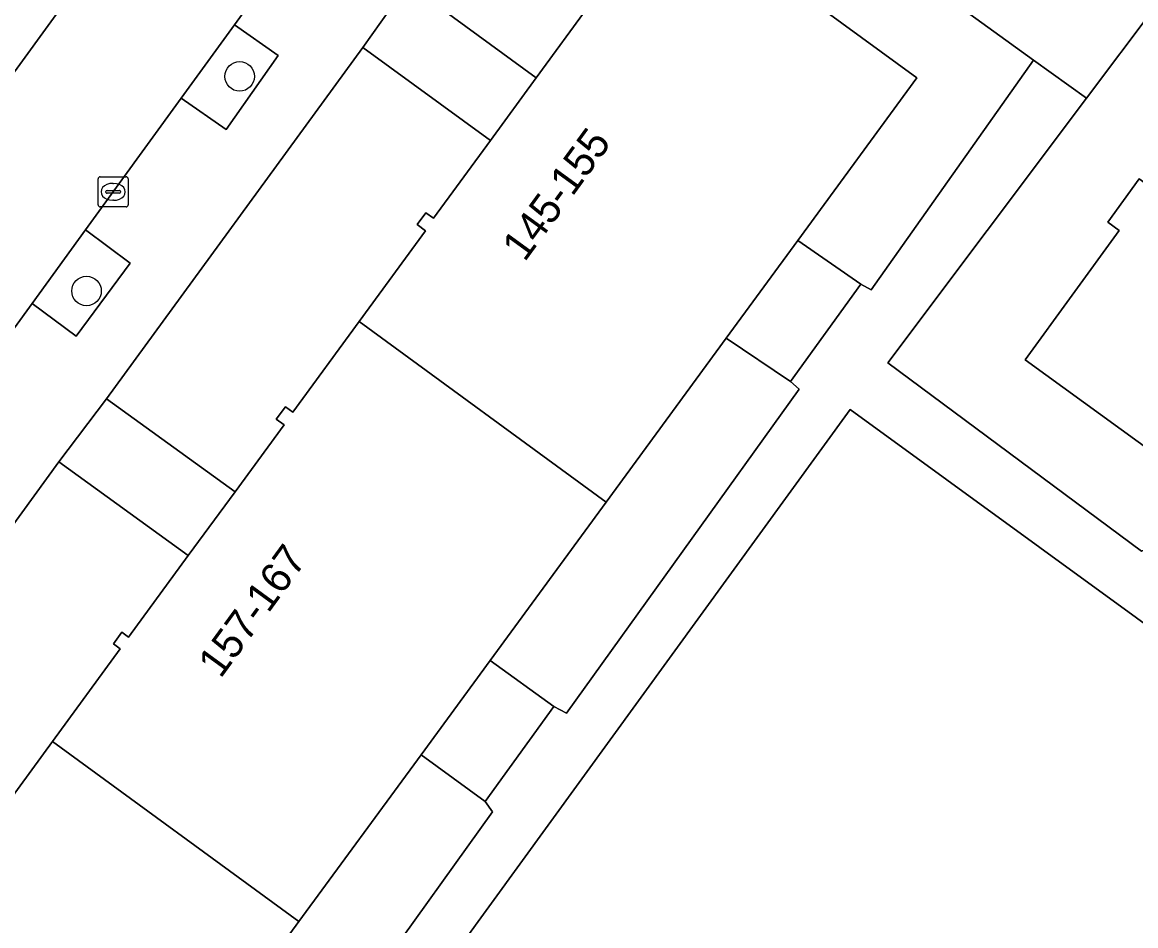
# Model space of a CAD drawing. Extents: x 160102 to 160934, y 382045 to 382923.
# Drawn here: x 160308.9 to 160345.72, y 382406.82 to 382436.72 of the extents above; entities that cross this region are included whole.
import ezdxf

# ---------------------------------------------------------------- set-up
doc = ezdxf.new("R2010")
doc.units = 0
for name, color, linetype in [('IMGEO_Boom', 7, 'Continuous'), ('IMGEO_Groenvoorziening', 7, 'Continuous'), ('IMGEO_Kolk', 7, 'Continuous'), ('IMGEO_Pand', 7, 'Continuous'), ('IMGEO_Pand_nummerreeks', 7, 'Continuous'), ('IMGEO_Parkeervlak_open', 7, 'Continuous'), ('IMGEO_Rijbaan_lokaal_open', 7, 'Continuous'), ('IMGEO_Voetpad_op_trap', 7, 'Continuous'), ('IMGEO_Voetpad_open', 7, 'Continuous')]:
    doc.layers.add(name, color=color, linetype=linetype)

msp = doc.modelspace()

# ---------------------------------------------------------------- linework, layer by layer
at = {"layer": 'IMGEO_Boom'}
for centre in [(160316.088, 382434.925), (160311.025, 382427.824)]:
    msp.add_circle(centre, 0.489, dxfattribs=at)
at = {"layer": 'IMGEO_Groenvoorziening'}
for points in [[(160326.042, 382443.886), (160321.653, 382437.992), (160325.889, 382434.874), (160327.67, 382437.308), (160327.431, 382437.483), (160327.719, 382437.877), (160327.954, 382437.705), (160329.995, 382440.493), (160329.751, 382440.671), (160330.034, 382441.058), (160332.743, 382439.075), (160333.021, 382439.455), (160334.448, 382438.411), (160334.173, 382438.035), (160338.483, 382434.88), (160334.541, 382429.494), (160336.63, 382428.051), (160336.971, 382427.863), (160342.342, 382435.462), (160330.141, 382444.298)], [(160370.829, 382398.747), (160336.272, 382423.908), (160301.535, 382376.068), (160301.385, 382375.861), (160326.781, 382357.302), (160333.47, 382352.414)]]:
    msp.add_lwpolyline(points, dxfattribs=at)
for points in [[(160345.836, 382431.539), (160346.277, 382431.219), (160348.196, 382433.864), (160348.496, 382433.646), (160348.355, 382433.452), (160351.228, 382431.367), (160351.397, 382431.599), (160351.776, 382431.324), (160351.609, 382431.094), (160354.123, 382429.27), (160355.13, 382430.78), (160346.323, 382437.183), (160344.086, 382434.199), (160337.524, 382425.446), (160345.91, 382419.22), (160346.099, 382419.291), (160347.73, 382421.428), (160342.062, 382425.541), (160345.171, 382429.825), (160344.791, 382430.1)], [(160314.157, 382434.207), (160315.637, 382433.164), (160317.362, 382435.613), (160315.915, 382436.632)], [(160322.237, 382429.818), (160321.957, 382430.023), (160322.243, 382430.415), (160322.493, 382430.232), (160324.377, 382432.807), (160320.164, 382435.884), (160311.684, 382424.258), (160315.935, 382421.18), (160317.556, 382423.395), (160317.3, 382423.582), (160317.602, 382423.994), (160317.845, 382423.816), (160320.041, 382426.817)], [(160309.224, 382427.412), (160310.684, 382426.332), (160312.472, 382428.749), (160310.991, 382429.844)], [(160334.588, 382424.579), (160334.297, 382424.828), (160332.174, 382426.259), (160328.208, 382420.84), (160324.37, 382415.595), (160326.472, 382414.075), (160326.893, 382413.858)], [(160312.135, 382415.982), (160311.912, 382416.146), (160312.196, 382416.535), (160312.417, 382416.373), (160314.389, 382419.068), (160310.105, 382422.17), (160301.387, 382410.162), (160305.61, 382407.024), (160307.41, 382409.484), (160307.146, 382409.677), (160307.414, 382410.043), (160307.657, 382409.865), (160309.896, 382412.923)], [(160324.45, 382410.594), (160324.208, 382410.933), (160322.085, 382412.472), (160318.049, 382406.957), (160314.189, 382401.682), (160316.293, 382400.219), (160316.804, 382399.911)]]:
    msp.add_lwpolyline(points, close=True, dxfattribs=at)
at = {"layer": 'IMGEO_Kolk'}
for p, q in [((160311.405, 382430.679), (160311.405, 382431.531)), ((160311.48, 382431.605), (160312.332, 382431.605)), ((160312.406, 382431.531), (160312.406, 382430.679)), ((160311.893, 382431.385), (160311.918, 382431.385)), ((160311.664, 382431.099), (160311.664, 382431.111)), ((160312.102, 382431.062), (160311.704, 382431.062)), ((160311.707, 382431.148), (160312.105, 382431.148)), ((160311.916, 382430.825), (160311.891, 382430.825)), ((160312.148, 382431.111), (160312.148, 382431.099)), ((160312.332, 382430.605), (160311.48, 382430.605))]:
    msp.add_line(p, q, dxfattribs=at)
for points in [[(160311.405, 382430.679), (160311.405, 382431.531)], [(160311.48, 382431.605), (160312.332, 382431.605)], [(160312.406, 382431.531), (160312.406, 382430.679)], [(160312.332, 382430.605), (160311.48, 382430.605)]]:
    msp.add_lwpolyline(points, dxfattribs=at)
for centre, radius, start, end in [((160311.482, 382431.529), 0.0765, 91.552, 178.448), ((160311.482, 382431.529), 0.0765, 91.552, 178.448), ((160312.33, 382431.529), 0.0765, 1.552, 88.448), ((160312.33, 382431.529), 0.0765, 1.552, 88.448), ((160311.704, 382431.108), 0.0403, 85.8775, 175.7526), ((160311.701, 382431.098), 0.0366, 178.938, 274.7102), ((160312.105, 382431.105), 0.043, 264.8664, 352.4533), ((160312.109, 382431.11), 0.0386, 1.7309, 96.639), ((160311.482, 382430.681), 0.0765, 181.552, 268.448), ((160311.482, 382430.681), 0.0765, 181.552, 268.448), ((160312.33, 382430.681), 0.0765, 271.552, 358.448), ((160312.33, 382430.681), 0.0765, 271.552, 358.448)]:
    msp.add_arc(centre, radius, start, end, dxfattribs=at)
for centre, major_axis, ratio, start_param, end_param in [((160311.892, 382431.105), (-0.387, 0.002), 0.722429, 4.712389, 7.853982), ((160311.917, 382431.105), (-0.39, 0.002), 0.717154, 1.570796, 4.712389)]:
    msp.add_ellipse(centre, major_axis=major_axis, ratio=ratio, start_param=start_param, end_param=end_param, dxfattribs=at)
at = {"layer": 'IMGEO_Pand'}
for points in [[(160338.483, 382434.88), (160334.173, 382438.035), (160334.448, 382438.411), (160333.021, 382439.455), (160332.743, 382439.075), (160330.034, 382441.058), (160329.751, 382440.671), (160329.995, 382440.493), (160327.954, 382437.705), (160327.719, 382437.877), (160327.431, 382437.483), (160327.67, 382437.308), (160325.889, 382434.874), (160324.377, 382432.807), (160322.493, 382430.232), (160322.243, 382430.415), (160321.957, 382430.023), (160322.237, 382429.818), (160320.041, 382426.817), (160328.208, 382420.84), (160332.174, 382426.259), (160334.541, 382429.494)], [(160356.176, 382427.78), (160354.123, 382429.27), (160351.609, 382431.094), (160351.776, 382431.324), (160351.397, 382431.599), (160351.228, 382431.367), (160348.355, 382433.452), (160348.496, 382433.646), (160348.196, 382433.864), (160346.277, 382431.219), (160345.836, 382431.539), (160344.791, 382430.1), (160345.171, 382429.825), (160342.062, 382425.541), (160347.73, 382421.428), (160350.837, 382419.173), (160356.188, 382415.289), (160362.154, 382423.509), (160359.103, 382425.723), (160359.222, 382425.887), (160358.82, 382426.179), (160358.668, 382425.971)], [(160328.208, 382420.84), (160320.041, 382426.817), (160317.845, 382423.816), (160317.602, 382423.994), (160317.3, 382423.582), (160317.556, 382423.395), (160315.935, 382421.18), (160314.389, 382419.068), (160312.417, 382416.373), (160312.196, 382416.535), (160311.912, 382416.146), (160312.135, 382415.982), (160309.896, 382412.923), (160318.049, 382406.957), (160322.085, 382412.472), (160324.37, 382415.595)], [(160318.049, 382406.957), (160309.896, 382412.923), (160307.657, 382409.865), (160307.414, 382410.043), (160307.146, 382409.677), (160307.41, 382409.484), (160305.61, 382407.024), (160304.093, 382404.95), (160302.264, 382402.451), (160302.04, 382402.614), (160301.746, 382402.213), (160301.968, 382402.051), (160299.756, 382399.029), (160307.89, 382393.076), (160311.897, 382398.552), (160314.189, 382401.682)]]:
    msp.add_lwpolyline(points, close=True, dxfattribs=at)
at = {"layer": 'IMGEO_Parkeervlak_open'}
msp.add_lwpolyline([(160294.103, 382415.076), (160350.285, 382492.403), (160348.458, 382493.72), (160295.236, 382420.526), (160294.487, 382419.495)], dxfattribs=at)
at = {"layer": 'IMGEO_Rijbaan_lokaal_open'}
msp.add_lwpolyline([(160353.587, 382490.022), (160350.285, 382492.403), (160294.103, 382415.076), (160282.644, 382399.239), (160286.754, 382396.408), (160289.282, 382399.909), (160291.056, 382402.365), (160297.372, 382411.107), (160299.14, 382413.539), (160304.095, 382420.356), (160305.885, 382422.819), (160309.224, 382427.412), (160310.991, 382429.844), (160314.157, 382434.207), (160315.915, 382436.632), (160319.987, 382442.247), (160321.768, 382444.703), (160324.87, 382448.973), (160324.923, 382449.066), (160334.935, 382462.721)], dxfattribs=at)
at = {"layer": 'IMGEO_Voetpad_op_trap'}
for points in [[(160336.63, 382428.051), (160334.541, 382429.494), (160332.174, 382426.259), (160334.297, 382424.828)], [(160326.472, 382414.075), (160324.37, 382415.595), (160322.085, 382412.472), (160324.208, 382410.933)]]:
    msp.add_lwpolyline(points, close=True, dxfattribs=at)
at = {"layer": 'IMGEO_Voetpad_open'}
for points in [[(160320.164, 382435.884), (160321.653, 382437.992), (160326.042, 382443.886), (160329.452, 382451.247)], [(160324.87, 382448.973), (160321.768, 382444.703), (160323.241, 382443.632), (160321.456, 382441.178), (160319.987, 382442.247), (160315.915, 382436.632), (160317.362, 382435.613), (160315.637, 382433.164), (160314.157, 382434.207), (160310.991, 382429.844), (160312.472, 382428.749), (160310.684, 382426.332), (160309.224, 382427.412), (160305.885, 382422.819), (160307.365, 382421.721), (160305.552, 382419.276), (160304.095, 382420.356), (160299.14, 382413.539), (160300.597, 382412.502), (160298.853, 382410.053), (160297.372, 382411.107), (160291.056, 382402.365)], [(160330.141, 382444.298), (160342.342, 382435.462), (160344.086, 382434.199), (160346.323, 382437.183), (160355.13, 382430.78), (160357.258, 382429.311), (160369.038, 382420.633), (160369.144, 382420.555), (160370.988, 382419.193), (160371.177, 382419.054), (160378.769, 382413.727)], [(160276.49, 382394.271), (160277.133, 382393.503), (160278.042, 382394.289), (160284.277, 382386.902), (160286.52, 382389.88), (160289.787, 382394.218), (160291.277, 382396.257), (160299.818, 382407.964), (160301.387, 382410.162), (160310.105, 382422.17), (160311.684, 382424.258), (160320.164, 382435.884)], [(160363.061, 382406.781), (160363.18, 382407.011), (160359.997, 382409.254), (160359.858, 382409.104), (160349.132, 382416.887), (160349.192, 382417.077), (160346.099, 382419.291), (160345.91, 382419.22), (160337.524, 382425.446), (160344.086, 382434.199), (160342.342, 382435.462), (160336.971, 382427.863), (160336.63, 382428.051), (160334.297, 382424.828), (160334.588, 382424.579), (160326.893, 382413.858), (160326.472, 382414.075), (160324.208, 382410.933), (160324.45, 382410.594), (160316.804, 382399.911)], [(160301.535, 382376.068), (160336.272, 382423.908), (160370.829, 382398.747)]]:
    msp.add_lwpolyline(points, dxfattribs=at)
for points in [[(160320.164, 382435.884), (160324.377, 382432.807), (160325.889, 382434.874), (160321.653, 382437.992)], [(160310.105, 382422.17), (160314.389, 382419.068), (160315.935, 382421.18), (160311.684, 382424.258)]]:
    msp.add_lwpolyline(points, close=True, dxfattribs=at)

# ---------------------------------------------------------------- texts
at = {"layer": 'IMGEO_Pand_nummerreeks'}
for s, rotation, p in [('145-155', 53.9497, (160325.512, 382428.76)), ('157-167', 53.8638, (160315.455, 382414.975))]:
    msp.add_text(s, height=1, rotation=rotation, dxfattribs=at).set_placement(p)

doc.saveas('drawing.dxf')
